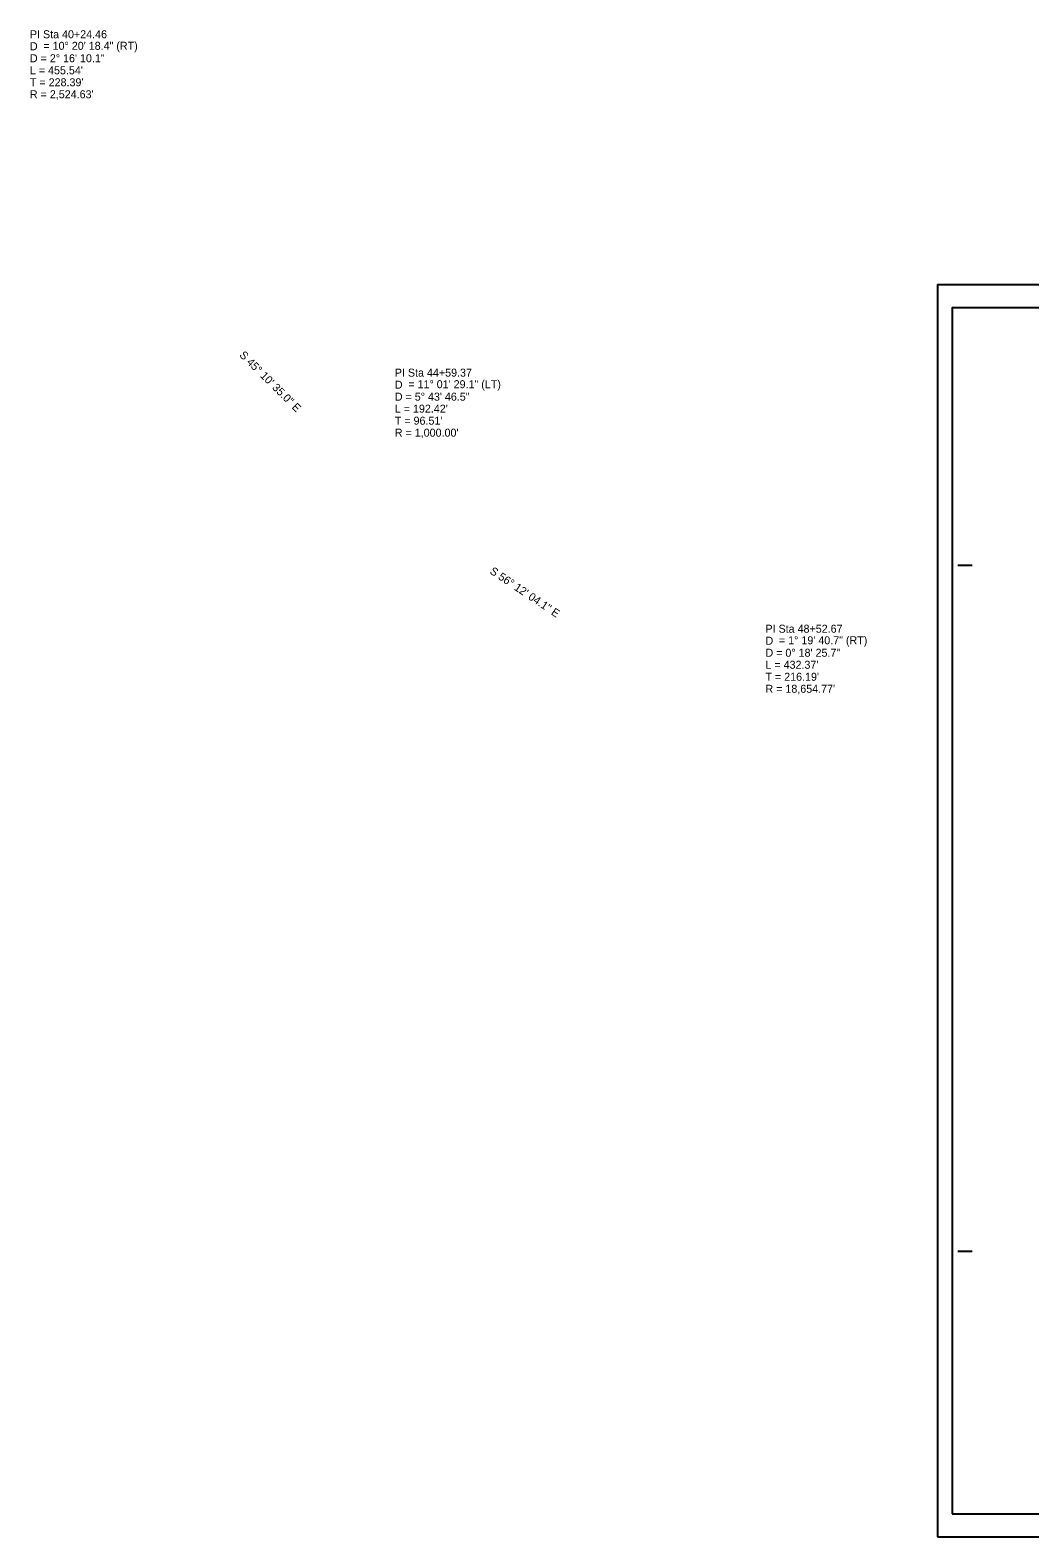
# Model space of a CAD drawing. Extents: x 928111 to 937215, y 684185 to 686530.
# Drawn here: x 930760 to 931634, y 684185 to 685503 of the extents above; entities that cross this region are included whole.
import ezdxf

# ---------------------------------------------------------------- set-up
doc = ezdxf.new("R2010")
doc.units = 0
for name, color, linetype in [('Exist Horizontal Alignment Curve and Spiral Data', 7, 'Continuous'), ('Exist Horizontal Alignment Direction Label', 7, 'Continuous'), ('Sheet Cutting Line CELL', 7, 'Continuous'), ('Sheet Plan CELL', 7, 'Continuous'), ('Sheet Plot Border Outside CELL', 7, 'Continuous')]:
    doc.layers.add(name, color=color, linetype=linetype)

msp = doc.modelspace()

# ---------------------------------------------------------------- linework, layer by layer
at = {"layer": 'Sheet Cutting Line CELL'}
for p, q in [((933236.8, 685280.2), (931553.3, 685280.2)), ((931553.3, 685280.2), (931553.3, 684185.2)), ((931553.3, 684185.2), (933236.8, 684185.2))]:
    msp.add_line(p, q, dxfattribs=at)
at = {"layer": 'Sheet Plan CELL'}
for p, q in [((931571.3, 685035.1), (931583.8, 685035.2)), ((931571.3, 684435.2), (931583.8, 684435.1))]:
    msp.add_line(p, q, dxfattribs=at)
msp.add_lwpolyline([(931566.3, 684205.2), (933232.3, 684205.2), (933232.3, 685260.2), (931566.3, 685260.2)], close=True, dxfattribs=at)
at = {"layer": 'Sheet Plot Border Outside CELL'}
msp.add_lwpolyline([(931553.3, 684185.2), (933236.8, 684185.2), (933236.8, 685280.2), (931553.3, 685280.2)], close=True, dxfattribs=at)

# ---------------------------------------------------------------- texts
at = {"layer": 'Exist Horizontal Alignment Curve and Spiral Data'}
for s, p in [('PI Sta 40+24.46', (930760, 685496)), ('D', (930760, 685485.5)), ('D = 2%%d 16\' 10.1"', (930760, 685475)), ('= 10%%d 20\' 18.4" (RT)', (930771.8, 685485.9)), ("L = 455.54'", (930760, 685464.5)), ("T = 228.39'", (930760, 685454)), ("R = 2,524.63'", (930760, 685443.5)), ('PI Sta 44+59.37', (931079, 685200)), ('D', (931079, 685189.5)), ('= 11%%d 01\' 29.1" (LT)', (931090.8, 685189.9)), ('D = 5%%d 43\' 46.5"', (931079, 685179)), ("T = 96.51'", (931079, 685158)), ("L = 192.42'", (931079, 685168.5)), ("R = 1,000.00'", (931079, 685147.5)), ('PI Sta 48+52.67', (931403, 684976)), ('D', (931403, 684965.5)), ('= 1%%d 19\' 40.7" (RT)', (931414.8, 684965.9)), ('D = 0%%d 18\' 25.7"', (931403, 684955)), ("T = 216.19'", (931403, 684934)), ("L = 432.37'", (931403, 684944.5)), ("R = 18,654.77'", (931403, 684923.5))]:
    msp.add_text(s, height=7, dxfattribs=at).set_placement(p)
at = {"layer": 'Exist Horizontal Alignment Direction Label'}
for s, rotation, p in [('S 45%%d 10\' 35.0" E', 315.1764, (930942.6, 685218.3)), ('S 56%%d 12\' 04.1" E', 326.2011, (931161.4, 685028.3))]:
    msp.add_text(s, height=7, rotation=rotation, dxfattribs=at).set_placement(p)

doc.saveas('drawing.dxf')
